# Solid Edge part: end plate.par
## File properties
Author: Binay
Template: sync ansi part.par
Last saved by: TIET
Revision: 12
Application: Solid Edge
Accuracy: 0.990
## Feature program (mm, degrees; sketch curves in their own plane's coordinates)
sketch for "unnamed Hole 1" plane through (74.0576, 73.9259, 6.35) normal (0, 0, 1) x-axis (1, 0, 0)
  hole centre (-38.8262, -36.609) bore radius 3.302
hole "unnamed Hole 1" through
pattern "unnamed Pattern 1" of "unnamed Hole 1"
hole "unnamed Hole 2" through
hole "unnamed Hole 3" through
hole "unnamed Hole 4" through
pattern "PatternOccurrence_5"  XCount = 4; XOffset = 90 deg
pattern "unnamed Pattern 3" of "unnamed Hole 1"
pattern "PatternOccurrence_1"  XCount = 2; YCount = 2; XOffset = 76.2 mm; YOffset = 76.2 mm
hole "unnamed Hole 5" through
hole "unnamed Hole 6" through
hole "unnamed Hole 7" through
sketch for "Hole_5" plane through (73.6248, 74.4917, 6.35) normal (0, 0, 1) x-axis (1, 0, 0)
  hole centre (-0.2934, 0.9253) bore radius 12.7
hole "Hole_5" diameter 25.4 through
pattern "unnamed Pattern 4" of "Hole_5"
sketch for "Hole_6" plane through (74.8044, 76.257, 6.35) normal (0, 0, 1) x-axis (1, 0, 0)
  hole centre (-1.4729, 19.7975) bore radius 2.413
hole "Hole_6" diameter 4.826 through
pattern "unnamed Pattern 2" of "Hole_6"
pattern "unnamed Pattern 5" of "Hole_6"
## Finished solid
Body 1: solid body, 15 faces, 30 edges, 8 vertices.
  Faces by surface: cylinder 9, plane 6
  Edges by curve: circle 18, line 12
Bounding box of the edges (mm): 101.600 x 101.600 x 12.700, from (22.5315, 24.617, -6.35) to (124.1315, 126.217, 6.35).
Cylindrical faces by radius (mm): R2.413 x4, R3.302 x4, R12.7 x1
Planar faces by outward normal: +x 1, +y 1, +z 1, -x 1, -y 1, -z 1
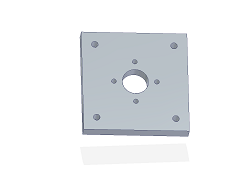
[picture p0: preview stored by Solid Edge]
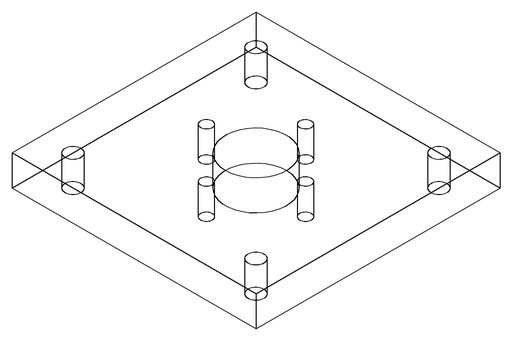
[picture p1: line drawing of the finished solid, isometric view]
